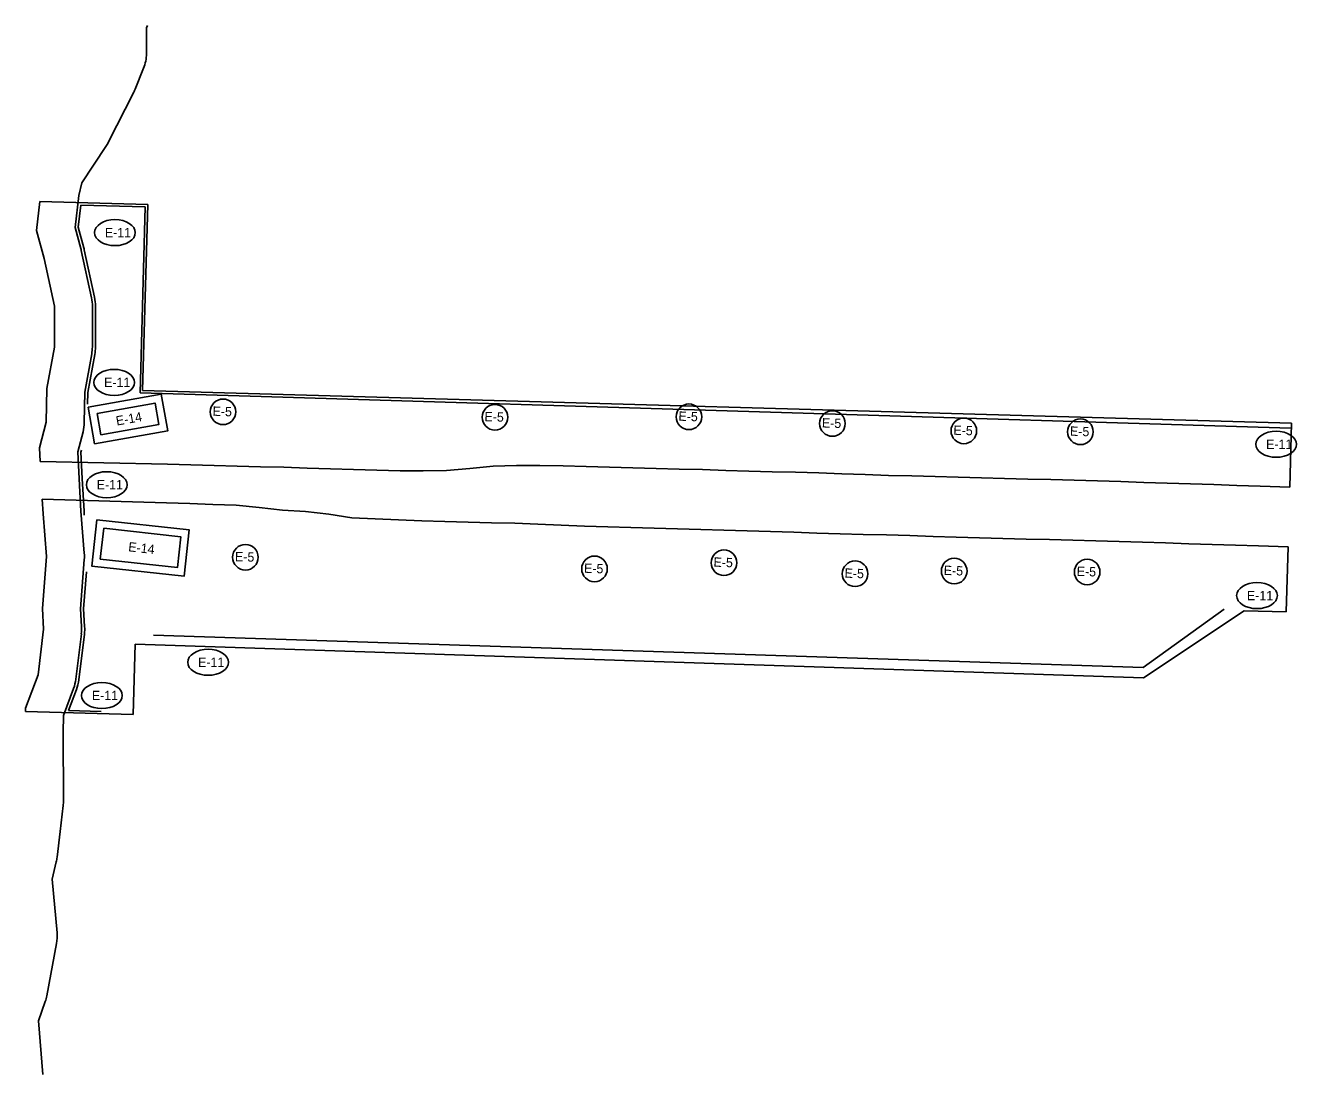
# Model space of a CAD drawing. Extents: x 977239 to 983725, y 1525948 to 1526901.
# Drawn here: x 982905 to 983725, y 1525953 to 1526629 of the extents above; entities that cross this region are included whole.
import ezdxf

# ---------------------------------------------------------------- set-up
doc = ezdxf.new("R2010")
doc.units = 0
for name, color, linetype in [('R_Erosion', 7, 'Continuous'), ('R_No Plot', 7, 'Continuous'), ('R_Water', 7, 'Continuous')]:
    doc.layers.add(name, color=color, linetype=linetype)

msp = doc.modelspace()

# ---------------------------------------------------------------- linework, layer by layer
at = {"layer": 'R_Erosion'}
for p, q in [((982940.35, 1526513.24), (982981.98, 1526512.06)), ((982981.98, 1526512.06), (982978.58, 1526392.11)), ((982949.24, 1526453.76), (982942.63, 1526484.39)), ((982978.58, 1526392.11), (983049.69, 1526390.1)), ((983049.69, 1526390.1), (983720.88, 1526369.29)), ((983625.67, 1526215.08), (983677.94, 1526252.57)), ((982939.13, 1526207.17), (982942.69, 1526236.58)), ((983625.67, 1526215.08), (982987.35, 1526235.82)), ((982932.46, 1526187.34), (982953.6, 1526186.74))]:
    msp.add_line(p, q, dxfattribs=at)
for points in [[(982942.31, 1526485.71), (982938.77, 1526498.87), (982940.35, 1526513.24)], [(982949.82, 1526421.72), (982949.83, 1526434.88), (982949.85, 1526448.03)], [(982944.77, 1526384.89), (982944.86, 1526392.38), (982949.37, 1526416.85)], [(982942.64, 1526313.28), (982942.43, 1526315.9), (982941.31, 1526336.85), (982940.4, 1526353.93), (982940.72, 1526355.15)], [(982942.84, 1526241.5), (982942.14, 1526252.8), (982944, 1526276.66)], [(982932.46, 1526187.34), (982937.58, 1526200.85)]]:
    msp.add_lwpolyline(points, dxfattribs=at)
for points in [[(982945.03, 1526382.91), (982992.28, 1526391.37), (982996.51, 1526367.75), (982949.26, 1526359.29)], [(982950.84, 1526378.87), (982988.24, 1526385.57), (982990.71, 1526371.79), (982953.3, 1526365.09)], [(982950.7, 1526310.3), (983010.35, 1526303.79), (983007.09, 1526273.97), (982947.45, 1526280.48)], [(982955.13, 1526304.79), (983004.83, 1526299.36), (983002.66, 1526279.48), (982952.96, 1526284.91)]]:
    msp.add_lwpolyline(points, close=True, dxfattribs=at)
for centre in [(983032.12, 1526379.9), (983207.52, 1526376.41), (983332.64, 1526376.69), (983425.18, 1526372.36), (983509.98, 1526367.63), (983585.19, 1526367.03), (983046.57, 1526286.12), (983355.26, 1526282.57), (983271.73, 1526278.64), (983439.8, 1526275.48), (983503.75, 1526277.23), (983589.52, 1526276.62)]:
    msp.add_circle(centre, 8.26, dxfattribs=at)
for centre, start, end in [((982916.23, 1526478.69), 12.1798, 15.05269), ((982922.85, 1526448.06), 359.94338, 12.1798), ((982922.82, 1526421.75), 349.55489, 359.94774), ((982915.89, 1526239.83), 353.09203, 3.54982), ((982912.33, 1526210.41), 339.26531, 353.09203)]:
    msp.add_arc(centre, 27, start, end, dxfattribs=at)
for centre in [(982962.37, 1526495.45), (982961.89, 1526398.87), (983711.45, 1526358.96), (982957.11, 1526332.9), (983699.07, 1526261.39), (983022.49, 1526218.39), (982953.97, 1526196.95)]:
    msp.add_ellipse(centre, major_axis=(13.15, 0), ratio=0.638788, dxfattribs=at)
at = {"layer": 'R_No Plot'}
for p, q in [((982913.94, 1526515.49), (982983.52, 1526513.52)), ((982983.52, 1526513.52), (982980.12, 1526393.57)), ((982980.12, 1526393.57), (983721.41, 1526372.56)), ((983721.41, 1526372.56), (983720.23, 1526331.33)), ((982996.3, 1526346.05), (982914.18, 1526347.97)), ((983011.3, 1526345.69), (982996.3, 1526346.05)), ((983026.29, 1526345.31), (983011.3, 1526345.69)), ((983041.29, 1526344.84), (983026.29, 1526345.31)), ((983056.36, 1526344.4), (983041.29, 1526344.84)), ((983071.36, 1526344.13), (983056.36, 1526344.4)), ((983086.36, 1526343.62), (983071.36, 1526344.13)), ((983101.35, 1526343.21), (983086.36, 1526343.62)), ((983116.34, 1526342.73), (983101.35, 1526343.21)), ((983131.34, 1526342.33), (983116.34, 1526342.73)), ((983146.33, 1526341.95), (983131.34, 1526342.33)), ((983161.31, 1526341.94), (983146.33, 1526341.95)), ((983176.29, 1526341.99), (983161.31, 1526341.94)), ((983191.32, 1526343.41), (983176.29, 1526341.99)), ((983206.39, 1526344.8), (983191.32, 1526343.41)), ((983221.43, 1526345.25), (983206.39, 1526344.8)), ((983236.46, 1526345.4), (983221.43, 1526345.25)), ((983251.44, 1526345.11), (983236.46, 1526345.4)), ((983266.43, 1526344.62), (983251.44, 1526345.11)), ((983281.42, 1526344.19), (983266.43, 1526344.62)), ((983296.42, 1526343.86), (983281.42, 1526344.19)), ((983311.41, 1526343.45), (983296.42, 1526343.86)), ((983326.41, 1526343.03), (983311.41, 1526343.45)), ((983341.4, 1526342.67), (983326.41, 1526343.03)), ((983356.39, 1526342.15), (983341.4, 1526342.67)), ((983371.38, 1526341.71), (983356.39, 1526342.15)), ((983386.37, 1526341.27), (983371.38, 1526341.71)), ((983401.37, 1526340.94), (983386.37, 1526341.27)), ((983416.36, 1526340.5), (983401.37, 1526340.94)), ((983431.35, 1526339.87), (983416.36, 1526340.5)), ((983446.4, 1526339.41), (983431.35, 1526339.87)), ((983461.38, 1526338.91), (983446.4, 1526339.41)), ((983476.38, 1526338.63), (983461.38, 1526338.91)), ((983491.37, 1526338.14), (983476.38, 1526338.63)), ((983506.37, 1526337.87), (983491.37, 1526338.14)), ((983521.36, 1526337.41), (983506.37, 1526337.87)), ((983536.2, 1526336.93), (983521.36, 1526337.41)), ((983551.19, 1526336.54), (983536.2, 1526336.93)), ((983566.19, 1526336.27), (983551.19, 1526336.54)), ((983581.18, 1526335.78), (983566.19, 1526336.27)), ((983596.17, 1526335.39), (983581.18, 1526335.78)), ((983611.17, 1526334.88), (983596.17, 1526335.39)), ((983626.16, 1526334.38), (983611.17, 1526334.88)), ((983641.14, 1526333.92), (983626.16, 1526334.38)), ((983656.14, 1526333.52), (983641.14, 1526333.92)), ((983671.13, 1526333.05), (983656.14, 1526333.52)), ((983686.12, 1526332.42), (983671.13, 1526333.05)), ((983701.11, 1526331.94), (983686.12, 1526332.42)), ((983717.92, 1526250.83), (983719.13, 1526292.89)), ((983625.93, 1526208.36), (983690.79, 1526251.67)), ((983690.79, 1526251.67), (983717.92, 1526250.83)), ((982974.2, 1526184.65), (982975.49, 1526230.01)), ((982975.49, 1526230.01), (983625.93, 1526208.36)), ((982904.64, 1526186.63), (982974.2, 1526184.65))]:
    msp.add_line(p, q, dxfattribs=at)
for points in [[(982914.18, 1526347.97), (982913.72, 1526356.67), (982918.12, 1526373.33), (982918.39, 1526394.97), (982923.32, 1526421.7), (982923.33, 1526434.9), (982923.35, 1526448.11), (982916.72, 1526478.81), (982911.88, 1526496.81), (982913.94, 1526515.49)], [(983720.23, 1526331.33), (983701.11, 1526331.94)], [(982915.49, 1526323.51), (982915.99, 1526314.13), (982917.09, 1526300.43), (982918.2, 1526286.69), (982915.57, 1526253.01), (982916.39, 1526239.82), (982912.82, 1526210.29), (982904.68, 1526188.8), (982904.64, 1526186.63)], [(983719.13, 1526292.89), (983700.11, 1526293.51), (983685.12, 1526294.02), (983670.13, 1526294.43), (983655.14, 1526294.86), (983640.15, 1526295.38), (983625.16, 1526295.84), (983610.16, 1526296.24), (983595.17, 1526296.7), (983580.18, 1526297.12), (983565.19, 1526297.5), (983550.2, 1526297.88), (983535.2, 1526298.3), (983520.09, 1526298.7), (983505.1, 1526299.11), (983490.1, 1526299.61), (983475.11, 1526300.13), (983460.13, 1526300.62), (983445.13, 1526300.89), (983430.18, 1526301.24), (983415.19, 1526301.73), (983400.2, 1526302.2), (983385.21, 1526302.69), (983370.22, 1526303.14), (983355.23, 1526303.7), (983340.24, 1526304.01), (983325.23, 1526304.4), (983310.24, 1526304.82), (983295.24, 1526305.36), (983280.25, 1526305.85), (983265.26, 1526306.28), (983250.27, 1526306.82), (983235.25, 1526307.44), (983220.27, 1526308.01), (983205.28, 1526308.4), (983190.28, 1526308.72), (983175.29, 1526309.27), (983160.29, 1526309.65), (983145.27, 1526310.27), (983115.26, 1526311.49), (983100.32, 1526314.01), (983085.39, 1526315.55), (983070.42, 1526316.59), (983055.46, 1526318.28), (983040.59, 1526319.76), (983025.61, 1526320.24), (983010.63, 1526320.83), (982995.63, 1526321.16), (982915.49, 1526323.51)]]:
    msp.add_lwpolyline(points, dxfattribs=at)
for centre in [(983032.12, 1526379.9), (983207.52, 1526376.41), (983332.64, 1526376.69), (983425.18, 1526372.36), (983509.98, 1526367.63), (983585.19, 1526367.03), (983046.57, 1526286.12), (983355.26, 1526282.57), (983271.73, 1526278.64), (983439.8, 1526275.48), (983503.75, 1526277.23), (983503.75, 1526277.23), (983589.52, 1526276.62)]:
    msp.add_circle(centre, 8.26, dxfattribs=at)
for centre in [(982957.11, 1526332.9), (983699.07, 1526261.39)]:
    msp.add_ellipse(centre, major_axis=(13.15, 0), ratio=0.638788, dxfattribs=at)
at = {"layer": 'R_Water'}
for p, q in [((982975.43, 1526587.99), (982980.86, 1526601.45)), ((982958.04, 1526553.5), (982974.54, 1526586.04)), ((982947.28, 1526453.33), (982940.67, 1526483.97)), ((982937.14, 1526207.41), (982940.71, 1526236.82)), ((982927.01, 1526109.35), (982928.97, 1526126.01)), ((982925.05, 1526092.68), (982927.01, 1526109.35)), ((982918.42, 1526003.33), (982924.73, 1526036.97))]:
    msp.add_line(p, q, dxfattribs=at)
for points in [[(982982.68, 1526610.85), (982982.65, 1526627.59), (982983.42, 1526629.06)], [(982940.38, 1526485.19), (982936.74, 1526498.71), (982939.02, 1526519.44), (982941.08, 1526527.55), (982956.6, 1526551.02)], [(982947.82, 1526421.73), (982947.83, 1526434.88), (982947.85, 1526448.03)], [(982942.62, 1526373.08), (982942.86, 1526392.57), (982947.41, 1526417.22)], [(982942.62, 1526288.69), (982941.51, 1526302.4), (982940.43, 1526315.77), (982939.32, 1526336.74), (982938.39, 1526354.14), (982941.79, 1526367.01)], [(982940.84, 1526241.38), (982940.13, 1526252.82), (982942.62, 1526284.74)], [(982929.14, 1526129.04), (982928.94, 1526173.02), (982929.11, 1526184.13), (982935.71, 1526201.56)], [(982925.05, 1526043.92), (982921.79, 1526078.48), (982924.52, 1526089.72)], [(982915.85, 1525952.55), (982913.07, 1525987.21), (982917.44, 1525999.66)]]:
    msp.add_lwpolyline(points, dxfattribs=at)
for centre, start, end in [((982957.68, 1526610.8), 338.01901, 0.10742), ((982952.25, 1526597.34), 333.10762, 338.01901), ((982935.75, 1526564.81), 326.52498, 333.10762), ((982916.23, 1526478.69), 12.1798, 15.05269), ((982922.85, 1526448.06), 359.94338, 12.1798), ((982922.82, 1526421.75), 349.55489, 359.94774), ((982917.62, 1526373.4), 345.20688, 359.26864), ((982917.7, 1526286.69), 355.54365, 4.60931), ((982915.89, 1526239.83), 353.09203, 3.54982), ((982912.33, 1526210.41), 339.26531, 353.09203), ((982904.14, 1526128.93), 353.29096, 0.26171), ((982902.18, 1526112.27), 353.28757, 353.29096), ((982900.22, 1526095.61), 346.39079, 353.28757), ((982900.16, 1526041.58), 349.37561, 5.38195), ((982893.85, 1526007.94), 340.65191, 349.37561)]:
    msp.add_arc(centre, 25, start, end, dxfattribs=at)

# ---------------------------------------------------------------- texts
at = {"layer": 'R_Erosion'}
for p in [(982955.87, 1526492.5), (982955.39, 1526395.92), (983704.95, 1526356.01), (982950.61, 1526329.95), (983692.57, 1526258.44), (983015.99, 1526215.44), (982947.47, 1526194)]:
    msp.add_text('E-11', height=5.999, dxfattribs=at).set_placement(p)
for s, height, rotation, p in [('E-5 ', 5.999, 358.09005, (983025.28, 1526377.4)), ('E-14', 6, 10.15073, (982963.58, 1526370.99)), ('E-5 ', 5.999, 358.09005, (983200.67, 1526373.91)), ('E-5 ', 5.999, 358.09005, (983325.8, 1526374.19)), ('E-5 ', 5.999, 358.09005, (983418.33, 1526369.86)), ('E-5 ', 5.999, 358.09005, (983503.14, 1526365.13)), ('E-5 ', 5.999, 358.09005, (983578.34, 1526364.53)), ('E-14', 6, 353.77189, (982970.77, 1526290)), ('E-5 ', 5.999, 358.09005, (983039.73, 1526283.62)), ('E-5 ', 5.999, 358.09005, (983348.42, 1526280.07)), ('E-5 ', 5.999, 358.09005, (983264.88, 1526276.14)), ('E-5 ', 5.999, 358.09005, (983432.95, 1526272.98)), ('E-5 ', 5.999, 358.09005, (983496.91, 1526274.73)), ('E-5 ', 5.999, 358.09005, (983582.67, 1526274.12))]:
    msp.add_text(s, height=height, rotation=rotation, dxfattribs=at).set_placement(p)
at = {"layer": 'R_Water'}
for rotation, p in [(355.68645, (983384.83, 1526363.65)), (0.34929, (983311.15, 1526235.92))]:
    msp.add_text('CONST. LIMITS', height=0.12, rotation=rotation, dxfattribs=at).set_placement(p)

doc.saveas('drawing.dxf')
